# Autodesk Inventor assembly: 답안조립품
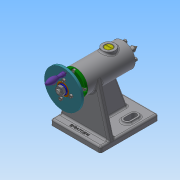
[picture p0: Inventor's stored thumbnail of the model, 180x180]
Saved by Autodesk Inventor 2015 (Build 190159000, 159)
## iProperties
Created: 2019-10
Part Number: 답안조립품
Document SubType Name: Assembly
Designer: user
Author: user
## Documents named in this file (18)
- C:\Users\user\Desktop\491004V1045\답안조립품.iam
- C:\Users\user\Desktop\491004V1045\본체.ipt
- C:\Users\user\Desktop\491004V1045\슬리브.ipt
- C:\Users\user\Desktop\491004V1045\중공축.ipt
- C:\Users\user\Desktop\491004V1045\센터홀더.ipt
- C:\Users\user\Desktop\491004V1045\멈춤나사 M3.ipt
- C:\Users\user\Desktop\491004V1045\센터.ipt
- C:\Users\user\Desktop\491004V1045\커버.ipt
- C:\Users\user\Desktop\491004V1045\부시.ipt
- C:\Users\user\Desktop\491004V1045\나사축.ipt
- C:\Users\user\Desktop\491004V1045\키 4 x 4 x 10.ipt
- C:\Users\user\Desktop\491004V1045\플랜지.ipt
- C:\Users\user\Desktop\491004V1045\돌림판.ipt
- C:\Users\user\Desktop\491004V1045\와셔.ipt
- C:\Users\user\Desktop\491004V1045\너트 M8.ipt
- C:\Users\user\Desktop\491004V1045\핸들.ipt
- C:\Users\user\Desktop\491004V1045\나사.ipt
- C:\Users\user\Desktop\491004V1045\볼트 M3.ipt
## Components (2 placed, 2 different names)
1. 플랜지:1 — 각도:1
2. 핸들:1
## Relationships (1: Angle 1)
- 각도:1 [Angle]: 플랜지:1
